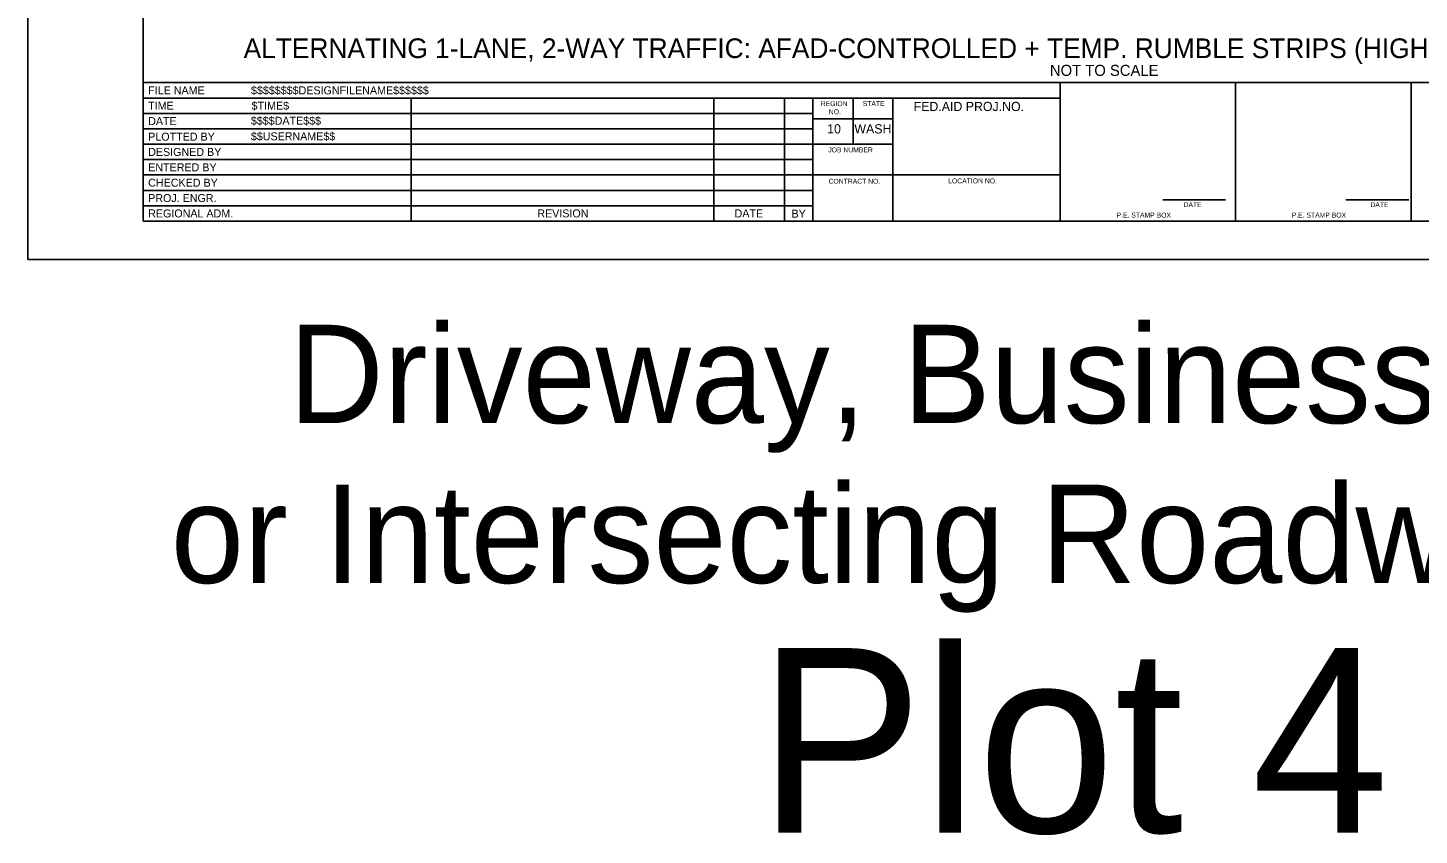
# Model space of a CAD drawing. Extents: x 99999.1 to 100095.7, y 99995 to 100010.7.
# Drawn here: x 100059.06 to 100070.38, y 99995.01 to 100001.57 of the extents above; entities that cross this region are included whole.
import ezdxf

# ---------------------------------------------------------------- set-up
doc = ezdxf.new("R2010")
doc.units = 0
for name, color, linetype in [('SH_DE_DetailHeading1Text', 7, 'Continuous'), ('SH_GI_PlotLimits', 7, 'Continuous'), ('SH_GI_SheetBorder', 7, 'Continuous'), ('SH_GI_SheetLocationText', 7, 'Continuous'), ('SH_GI_SheetTextInCells', 7, 'Continuous'), ('SH_GI_TitleBlockText', 7, 'Continuous')]:
    doc.layers.add(name, color=color, linetype=linetype)

msp = doc.modelspace()

# ---------------------------------------------------------------- linework, layer by layer
at = {"layer": 'SH_GI_PlotLimits'}
msp.add_lwpolyline([(100059.062, 99999.687), (100076.062, 99999.687), (100076.062, 100010.687), (100059.062, 100010.687)], close=True, dxfattribs=at)
at = {"layer": 'SH_GI_SheetBorder'}
for p, q in [((100060, 100010.375), (100060, 100000)), ((100060, 100001.126), (100075.75, 100001.126)), ((100067.457, 100000), (100067.457, 100001.126)), ((100068.883, 100000), (100068.883, 100001.126)), ((100070.309, 100001.126), (100070.309, 100000)), ((100060, 100001.001), (100067.457, 100001.001)), ((100062.179, 100001.001), (100062.179, 100000)), ((100064.641, 100001.001), (100064.641, 100000)), ((100065.216, 100001.001), (100065.216, 100000)), ((100065.445, 100001.001), (100065.445, 100000)), ((100065.772, 100000.625), (100065.772, 100001.001)), ((100066.096, 100000), (100066.096, 100001.001)), ((100060, 100000.876), (100062.182, 100000.876)), ((100062.182, 100000.876), (100065.447, 100000.876)), ((100066.096, 100000.831), (100065.447, 100000.831)), ((100060, 100000.751), (100062.182, 100000.751)), ((100062.182, 100000.751), (100065.447, 100000.751)), ((100060, 100000.625), (100065.447, 100000.625)), ((100066.096, 100000.625), (100065.447, 100000.625)), ((100060, 100000.5), (100065.447, 100000.5)), ((100060, 100000.375), (100065.447, 100000.375)), ((100067.457, 100000.375), (100065.447, 100000.375)), ((100060, 100000.25), (100065.447, 100000.25)), ((100060, 100000.125), (100065.447, 100000.125)), ((100068.29, 100000.173), (100068.802, 100000.173)), ((100069.78, 100000.173), (100070.291, 100000.173)), ((100060, 100000), (100075.75, 100000))]:
    msp.add_line(p, q, dxfattribs=at)

# ---------------------------------------------------------------- texts
at = {"layer": 'SH_DE_DetailHeading1Text'}
for s, height, p in [('ALTERNATING 1-LANE, 2-WAY TRAFFIC: AFAD-CONTROLLED + TEMP. RUMBLE STRIPS (HIGH VOLUME 45+ MPH HIGHWAYS)', 0.16, (100060.817, 100001.326)), ('NOT TO SCALE', 0.09, (100067.373, 100001.181))]:
    msp.add_text(s, height=height, rotation=360, dxfattribs=at).set_placement(p)
at = {"layer": 'SH_GI_SheetLocationText'}
for s, height, p in [('Driveway, Business Access,', 0.8, (100061.184, 99998.357)), ('or Intersecting Roadway Details', 0.8, (100060.225, 99997.057)), ('Plot 4', 1.5, (100065.001, 99995.027))]:
    msp.add_text(s, height=height, dxfattribs=at).set_placement(p)
at = {"layer": 'SH_GI_SheetTextInCells'}
for s, height, p in [('FILE NAME', 0.0651, (100060.041, 100001.031)), ('TIME', 0.0651, (100060.041, 100000.906)), ('REGION', 0.04, (100065.51, 100000.935)), ('NO.', 0.04, (100065.575, 100000.869)), ('STATE', 0.04, (100065.851, 100000.936)), ('FED.AID PROJ.NO.', 0.07506, (100066.265, 100000.895)), ('DATE', 0.0651, (100060.041, 100000.781)), ('10', 0.0751, (100065.562, 100000.713)), ('WASH', 0.0751, (100065.783, 100000.713)), ('PLOTTED BY', 0.0651, (100060.041, 100000.654)), ('DESIGNED BY', 0.06505, (100060.041, 100000.53)), ('JOB NUMBER', 0.04, (100065.571, 100000.559)), ('ENTERED BY', 0.0651, (100060.041, 100000.405)), ('CHECKED BY', 0.0651, (100060.041, 100000.28)), ('CONTRACT NO.', 0.04003, (100065.573, 100000.304)), ('LOCATION NO.', 0.04003, (100066.546, 100000.307)), ('PROJ. ENGR.', 0.06505, (100060.041, 100000.155)), ('REGIONAL ADM.', 0.06505, (100060.041, 100000.03)), ('REVISION', 0.0651, (100063.205, 100000.03)), ('DATE', 0.04, (100068.46, 100000.114)), ('DATE', 0.04, (100069.979, 100000.114)), ('DATE', 0.0651, (100064.809, 100000.03)), ('BY', 0.0651, (100065.272, 100000.028)), ('P.E. STAMP BOX', 0.04003, (100067.915, 100000.029)), ('P.E. STAMP BOX', 0.04003, (100069.339, 100000.029))]:
    msp.add_text(s, height=height, dxfattribs=at).set_placement(p)
at = {"layer": 'SH_GI_TitleBlockText'}
for s, height, p in [('$$$$$$$$DESIGNFILENAME$$$$$$', 0.06505, (100060.877, 100001.031)), ('$TIME$', 0.0651, (100060.882, 100000.906)), ('$$$$DATE$$$', 0.06505, (100060.876, 100000.784)), ('$$USERNAME$$', 0.06505, (100060.876, 100000.657))]:
    msp.add_text(s, height=height, dxfattribs=at).set_placement(p)

doc.saveas('drawing.dxf')
